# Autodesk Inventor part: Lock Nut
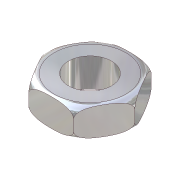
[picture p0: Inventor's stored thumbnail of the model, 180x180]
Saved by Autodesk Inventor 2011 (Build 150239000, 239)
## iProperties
Shininess: 77.0
Length Units: 11269
Angle Units: 11279
Time Units: 11290
Mass Units: 11283
Length Display Precision: 3
Angle Display Precision: 2
Created: 2002-02
Part Number: Lock Nut
Document SubType Name: Modeling
Designer: ***
Density: 1 g/cm^3
Density: 0.0
Volumn: 0.0
Area: 0.0
PropertySet Name: Model Information
Control State: 0
Master: False
Checked Out: False
Author: ***
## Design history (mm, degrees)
sketch "Sketch1"
  geometry: C1 r 12.5 at (0, 0)
  constraints: 1 centre point
  dimensions: "d0" = 25 diameter of C1
extrude "Extrusion1" new body sketch "Sketch1" stored distance "d1" = 8; taper "d2" = 0 deg
fillet "Fillet1" dims "d3" = 2.5
sketch "Sketch2"
  geometry: L1 (12.5, 0)-(6.25, -10.825); L2 (6.25, -10.825)-(-6.25, -10.825); L3 (-6.25, -10.825)-(-12.5, 0); L4 (-12.5, 0)-(-6.25, 10.825); L5 (-6.25, 10.825)-(6.25, 10.825); L6 (6.25, 10.825)-(12.5, 0); C1 r 10 at (0, 0) reference; 1 further point
  constraints: 12 end point, 1 coincident, 11 other
extrude "Extrusion2" sketch "Sketch2" stored distance "d4" = 12; taper "d5" = 0 deg
sketch "Sketch3"
  geometry: C1 r 10 at (0, 0) reference
hole "Hole1" sketch "Sketch3" at (0, 0) diameter "d6" = 12; stored, may be unused: countersink angle "d10" = 82 deg, drill point angle "d12" = 118 deg; dims "d7" = 6, "d8" = 4, "d9" = 2, "d11" = 8
body "Solid1"
